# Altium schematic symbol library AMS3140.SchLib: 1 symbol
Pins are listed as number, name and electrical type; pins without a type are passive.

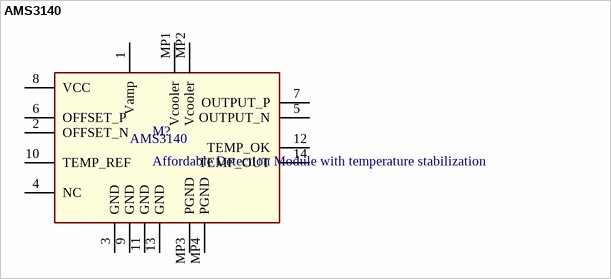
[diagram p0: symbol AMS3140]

## AMS3140
designator M?, comment Affordable Detection Module with temperature stabilization
Manufacturer: Amphenol ICC / Aorora; Part Number: 101R014FB110
pins: 1 Vamp, 2 OFFSET_N, 3 GND, 4 NC, 5 OUTPUT_N, 6 OFFSET_P, 7 OUTPUT_P, 8 VCC, 9 GND, 10 TEMP_REF, 11 GND, 12 TEMP_OK, 13 GND, 14 TEMP_OUT, MP1 Vcooler, MP2 Vcooler, MP3 PGND, MP4 PGND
